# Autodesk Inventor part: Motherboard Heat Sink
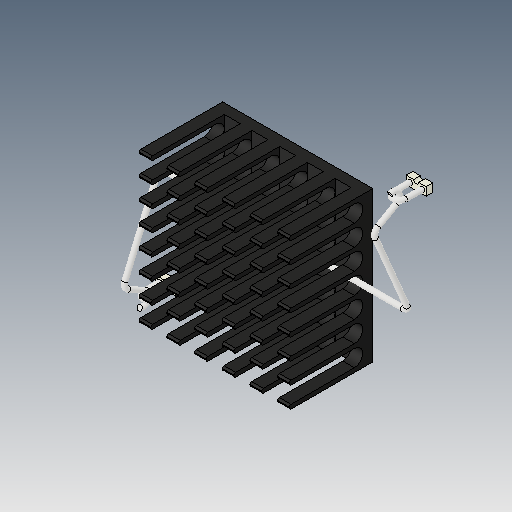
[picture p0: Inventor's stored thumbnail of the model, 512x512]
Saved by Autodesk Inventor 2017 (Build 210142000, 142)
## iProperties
Created: 2005-12
Part Number: Motherboard Heat Sink
Material: Generic
Document SubType Name: Modeling
Designer: DanielSeverino
Density: 1 g/cm^3
Appearance: Default
Author: DanielSeverino
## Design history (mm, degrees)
feature "Solid1"
feature "Solid1:1"
feature "Solid1:2"
feature "Solid1:3"
body "Solid2"
body "Solid3"
body "Solid4"
body "Solid5"
